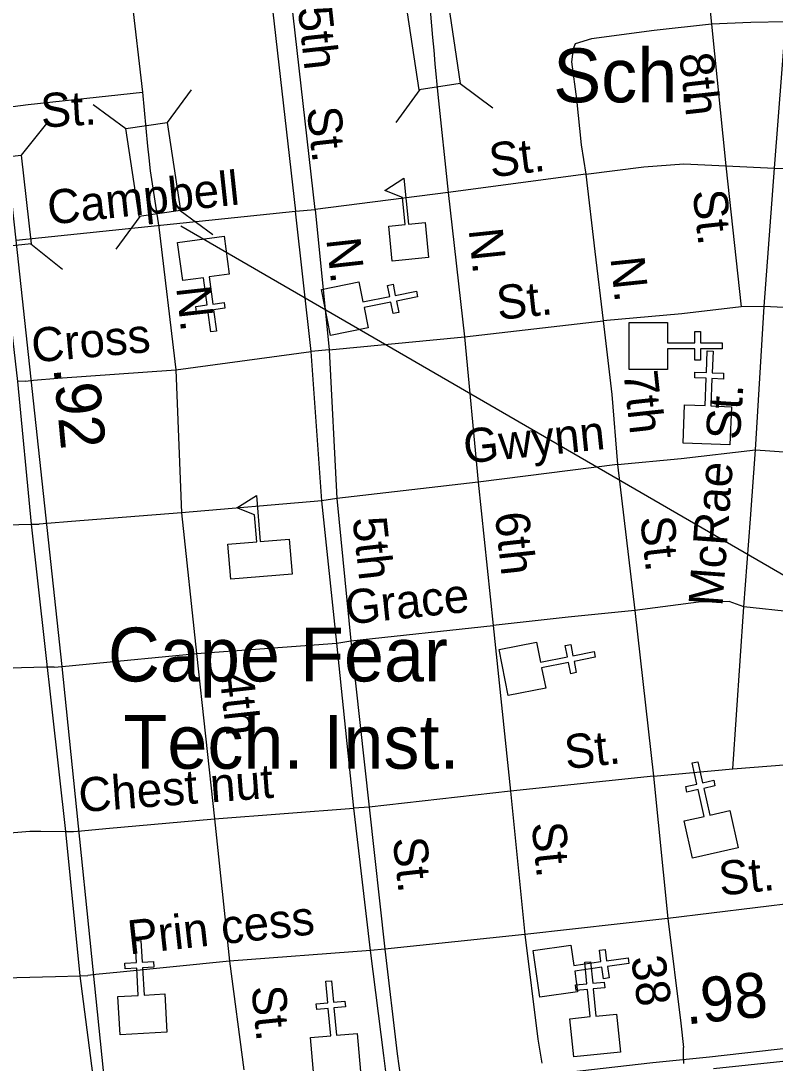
# Model space of a CAD drawing. Extents: x 2290055 to 2389491, y 66597 to 237875.
# Drawn here: x 2318340 to 2320442, y 178595 to 181498 of the extents above; entities that cross this region are included whole.
import ezdxf

# ---------------------------------------------------------------- set-up
doc = ezdxf.new("R2010")
doc.units = 0
for name, color, linetype in [('Exist Cultural Church CELL', 7, 'Continuous'), ('Exist Cultural Educational Facility College or University CELL', 7, 'Continuous'), ('Exist Cultural Educational Facility College or University Label', 7, 'Continuous'), ('Exist Cultural Educational Facility High CELL', 7, 'Continuous'), ('Exist Cultural Educational Facility High Label', 7, 'Continuous'), ('Exist Road Non-System Structure Non-Sys Other CELL', 7, 'Continuous'), ('Exist Road Non-System Structure Non-Sys Other Number Label', 7, 'Continuous'), ('Exist Road Non-System Type 51', 7, 'Continuous'), ('Exist Road Non-System Type 51 Label', 7, 'Continuous'), ('Exist Road Primary US Divided Attributed', 7, 'Continuous'), ('Exist Road Primary US Mileage Hundredths English Label', 7, 'Continuous'), ('Exist Road Secondary Mileage Hundredths English Label', 7, 'Continuous'), ('Exist Road Secondary Structure Standard Bridge CELL', 7, 'Continuous'), ('Exist Road Secondary Type 51 Divided Attributed', 7, 'Continuous')]:
    doc.layers.add(name, color=color, linetype=linetype)

msp = doc.modelspace()

# ---------------------------------------------------------------- linework, layer by layer
at = {"layer": 'Exist Cultural Church CELL'}
for points in [[(2318921, 180792.3), (2318864.6, 180784.4), (2318875, 180709), (2318906.7, 180713.4), (2318908.9, 180697.6), (2318877.2, 180693.2), (2318885.4, 180633.6), (2318869.5, 180631.4), (2318861.3, 180691), (2318829.6, 180686.6), (2318827.4, 180702.5), (2318859.1, 180706.8), (2318848.7, 180782.3), (2318791.6, 180774.5), (2318777.1, 180880), (2318906.5, 180897.8)], [(2319281.9, 180770.4), (2319293.2, 180714.6), (2319367.9, 180729.5), (2319361.6, 180760.9), (2319377.3, 180764), (2319383.5, 180732.6), (2319442.5, 180744.4), (2319445.7, 180728.7), (2319386.7, 180716.9), (2319393, 180685.5), (2319377.3, 180682.4), (2319371, 180713.8), (2319296.4, 180698.9), (2319307.5, 180642.3), (2319203.2, 180621.4), (2319177.6, 180749.5)], [(2320142, 180657.3), (2320142.2, 180600.4), (2320218.3, 180600.4), (2320218.3, 180632.4), (2320234.3, 180632.4), (2320234.3, 180600.4), (2320294.4, 180600.4), (2320294.4, 180584.3), (2320234.3, 180584.3), (2320234.3, 180552.3), (2320218.3, 180552.3), (2320218.3, 180584.3), (2320142.2, 180584.3), (2320142, 180526.7), (2320035.6, 180526.7), (2320035.6, 180657.3)], [(2320189.8, 180428.2), (2320246.7, 180425.9), (2320249.9, 180502), (2320217.9, 180503.4), (2320218.6, 180519.3), (2320250.5, 180518), (2320253, 180578.1), (2320269.1, 180577.4), (2320266.6, 180517.3), (2320298.5, 180516), (2320297.9, 180500), (2320265.9, 180501.4), (2320262.7, 180425.3), (2320320.3, 180422.8), (2320315.9, 180316.4), (2320185.4, 180321.8)], [(2319777, 179767.1), (2319788.3, 179711.3), (2319863, 179726.2), (2319856.7, 179757.6), (2319872.4, 179760.8), (2319878.6, 179729.4), (2319937.6, 179741.2), (2319940.7, 179725.4), (2319881.8, 179713.7), (2319888, 179682.3), (2319872.4, 179679.2), (2319866.1, 179710.5), (2319791.4, 179695.6), (2319802.6, 179639.1), (2319698.2, 179618.2), (2319672.6, 179746.3)], [(2320188.5, 179269.5), (2320244.1, 179281.9), (2320227.6, 179356.3), (2320196.3, 179349.3), (2320192.8, 179364.9), (2320224.1, 179371.8), (2320211, 179430.6), (2320226.7, 179434), (2320239.7, 179375.3), (2320271, 179382.3), (2320274.4, 179366.7), (2320243.2, 179359.7), (2320259.7, 179285.4), (2320316, 179297.8), (2320339.1, 179193.9), (2320211.6, 179165.5)], [(2318610.5, 178779.8), (2318667.4, 178783.2), (2318662.9, 178859.2), (2318630.9, 178857.4), (2318630, 178873.3), (2318662, 178875.2), (2318658.4, 178935.2), (2318674.4, 178936.2), (2318678, 178876.1), (2318709.9, 178878), (2318710.8, 178862.1), (2318678.9, 178860.2), (2318683.4, 178784.2), (2318740.9, 178787.4), (2318747.2, 178681.2), (2318616.8, 178673.5)], [(2319873.1, 178922.9), (2319881.2, 178866.6), (2319956.6, 178877.3), (2319952.1, 178909), (2319967.9, 178911.3), (2319972.4, 178879.6), (2320032, 178888.1), (2320034.2, 178872.2), (2319974.7, 178863.7), (2319979.2, 178832), (2319963.4, 178829.8), (2319958.9, 178861.5), (2319883.5, 178850.7), (2319891.5, 178793.6), (2319786.1, 178778.6), (2319767.7, 178907.9)], [(2319870.2, 178718.3), (2319926.8, 178724.1), (2319919.3, 178799.8), (2319887.4, 178796.6), (2319885.8, 178812.5), (2319917.7, 178815.7), (2319911.7, 178875.6), (2319927.6, 178877.2), (2319933.6, 178817.3), (2319965.4, 178820.5), (2319967, 178804.6), (2319935.2, 178801.4), (2319942.8, 178725.7), (2320000.2, 178731.3), (2320010.8, 178625.4), (2319880.8, 178612.4)], [(2319146.8, 178665.7), (2319203.5, 178670.9), (2319196.6, 178746.8), (2319164.8, 178743.9), (2319163.3, 178759.8), (2319195.2, 178762.7), (2319189.7, 178822.6), (2319205.7, 178824), (2319211.1, 178764.1), (2319243, 178767), (2319244.5, 178751.1), (2319212.6, 178748.2), (2319219.5, 178672.4), (2319276.9, 178677.5), (2319286.6, 178571.5), (2319156.5, 178559.6)]]:
    msp.add_lwpolyline(points, close=True, dxfattribs=at)
at = {"layer": 'Exist Cultural Educational Facility College or University CELL'}
msp.add_lwpolyline([(2318925, 179942.3), (2318916.8, 180039.8), (2318997.6, 180046.6), (2318991.3, 180121.4), (2318942.4, 180141.7), (2318996.5, 180175.4), (2319007.1, 180047.4), (2319087.9, 180054.1), (2319096, 179956.5)], close=True, dxfattribs=at)
at = {"layer": 'Exist Cultural Educational Facility High CELL'}
msp.add_lwpolyline([(2319374.9, 180828.5), (2319365.2, 180925.9), (2319411, 180930.5), (2319403.5, 181005.2), (2319354.3, 181024.7), (2319407.7, 181059.4), (2319420.5, 180931.5), (2319466.4, 180936.1), (2319476.1, 180838.6)], close=True, dxfattribs=at)
at = {"layer": 'Exist Road Non-System Structure Non-Sys Other CELL'}
for p, q in [((2318814.9, 181305.8), (2318747.6, 181214.7)), ((2319452.1, 181306), (2319384.9, 181214.9)), ((2319564.1, 181322.8), (2319655.1, 181255.6)), ((2318542.1, 181264.7), (2318633.1, 181197.5)), ((2318672.1, 180952.7), (2318604.9, 180861.6)), ((2318784, 180969.5), (2318875.1, 180902.3))]:
    msp.add_line(p, q, dxfattribs=at)
for points in [[(2319527.7, 181568), (2319564.6, 181322.9), (2319450.1, 181305.7), (2319413.2, 181550.8)], [(2318747.6, 181214.7), (2318784.6, 180969.6), (2318670.1, 180952.4), (2318633.1, 181197.5)]]:
    msp.add_lwpolyline(points, close=True, dxfattribs=at)
at = {"layer": 'Exist Road Non-System Structure Non-Sys Other Number Label'}
msp.add_line((2318786.3, 180926.4), (2320782.2, 179770.1), dxfattribs=at)
at = {"layer": 'Exist Road Non-System Type 51'}
for p, q in [((2319017.2, 181740.6), (2319105.9, 180967.2)), ((2319160, 180972.3), (2319072.3, 181747.6)), ((2318632.2, 181703.5), (2318678.8, 181299.3)), ((2320264.3, 181488.5), (2320304.2, 181093.9)), ((2320440.3, 181087.5), (2320472.1, 181494.7)), ((2319487.4, 181451.7), (2319490.6, 181416.4)), ((2319490.6, 181416.4), (2319494.1, 181377.9)), ((2318360.5, 181264.9), (2318678.8, 181299.3)), ((2318678.8, 181299.3), (2318692.7, 181148.2)), ((2317861.3, 181201.4), (2318360.5, 181264.9)), ((2318692.7, 181148.2), (2318696.5, 181116.4)), ((2318696.5, 181116.4), (2318700.8, 181080.1)), ((2318700.8, 181080.1), (2318724.3, 180923.4)), ((2319914.9, 181070.6), (2319530.7, 181019.3)), ((2320304.2, 181093.9), (2320440.3, 181087.5)), ((2320304.2, 181093.9), (2320347.7, 180701.5)), ((2320411.6, 180702.1), (2320440.3, 181087.5)), ((2319530.7, 181019.3), (2319160, 180972.3)), ((2319530.7, 181019.3), (2319576.8, 180617.2)), ((2318326.7, 180887.2), (2319105.9, 180967.2)), ((2319105.9, 180967.2), (2319160, 180972.3)), ((2319149.1, 180576.7), (2319105.9, 180967.2)), ((2319160, 180972.3), (2319198.9, 180581)), ((2318724.3, 180923.4), (2318772, 180525.6)), ((2320411.6, 180702.1), (2320347.7, 180701.5)), ((2320387.4, 180303), (2320411.6, 180702.1)), ((2319576.8, 180617.2), (2319962.9, 180662.3)), ((2319198.9, 180581), (2319576.8, 180617.2)), ((2319576.8, 180617.2), (2319614.8, 180212.4)), ((2318772, 180525.6), (2319149.1, 180576.7)), ((2319198.9, 180581), (2319149.1, 180576.7)), ((2319178.7, 180161), (2319149.1, 180576.7)), ((2319198.9, 180581), (2319220.5, 180166.9)), ((2318442.9, 180502.7), (2318772, 180525.6)), ((2318772, 180525.6), (2318787.8, 180127.8)), ((2318353.2, 180494.5), (2318330.6, 180493.6)), ((2318353.2, 180494.5), (2318375.7, 180496.6)), ((2318375.7, 180496.6), (2318375.8, 180496.6)), ((2318375.8, 180496.6), (2318442.9, 180502.7)), ((2320002.7, 180261.8), (2319614.8, 180212.4)), ((2320002.7, 180261.8), (2320051, 179855.5)), ((2319614.8, 180212.4), (2319220.5, 180166.9)), ((2319614.8, 180212.4), (2319656.5, 179813.9)), ((2319178.7, 180161), (2318787.8, 180127.8)), ((2319220.5, 180166.9), (2319178.7, 180161)), ((2319220.3, 179764.5), (2319178.7, 180161)), ((2319220.5, 180166.9), (2319260.1, 179770.4)), ((2318787.8, 180127.8), (2318481.3, 180103.2)), ((2318787.8, 180127.8), (2318829.3, 179735.3)), ((2318300.6, 180094.1), (2318368.5, 180095.5)), ((2318368.5, 180095.5), (2318391, 180096)), ((2318413.8, 180097.8), (2318391, 180096)), ((2318481.3, 180103.2), (2318413.8, 180097.8)), ((2320051, 179855.5), (2320103.4, 179393.5)), ((2320324.5, 179414.1), (2320354.8, 179865.6)), ((2319260.1, 179770.4), (2319656.5, 179813.9)), ((2319656.5, 179813.9), (2319704.7, 179351.8)), ((2318829.3, 179735.3), (2319220.3, 179764.5)), ((2319220.3, 179764.5), (2319260.1, 179770.4)), ((2319268.4, 179304.3), (2319220.3, 179764.5)), ((2319260.1, 179770.4), (2319310.3, 179308)), ((2318522.6, 179706.1), (2318829.3, 179735.3)), ((2318829.3, 179735.3), (2318879.7, 179275.2)), ((2318455, 179699.7), (2318522.6, 179706.1)), ((2318410.3, 179697.1), (2318342.2, 179695.5)), ((2318432.7, 179697.6), (2318410.3, 179697.1)), ((2318432.7, 179697.6), (2318455, 179699.7)), ((2320103.4, 179393.5), (2320324.5, 179414.1)), ((2320324.5, 179414.1), (2320478.2, 179426.4)), ((2320103.4, 179393.5), (2319704.7, 179351.8)), ((2320103.4, 179393.5), (2320143.1, 178997)), ((2319704.7, 179351.8), (2319310.3, 179308)), ((2319704.7, 179351.8), (2319744.8, 178953)), ((2318879.7, 179275.2), (2319268.4, 179304.3)), ((2319310.3, 179308), (2319268.4, 179304.3)), ((2319314.3, 178908.1), (2319268.4, 179304.3)), ((2319310.3, 179308), (2319354.2, 178911.6)), ((2318577, 179247.8), (2318879.7, 179275.2)), ((2318879.7, 179275.2), (2318921.3, 178878.4)), ((2318396, 179240.4), (2318464.6, 179239.8)), ((2318464.6, 179239.8), (2318486.9, 179239.6)), ((2318486.9, 179239.6), (2318509.4, 179241.6)), ((2318509.4, 179241.6), (2318577, 179247.8)), ((2320527.2, 179044), (2320143.1, 178997)), ((2320143.1, 178997), (2319744.8, 178953)), ((2320143.1, 178997), (2320179.6, 178705.8)), ((2319744.8, 178953), (2319354.2, 178911.6)), ((2319744.8, 178953), (2319781.1, 178661.6)), ((2319314.3, 178908.1), (2318921.3, 178878.4)), ((2319354.2, 178911.6), (2319314.3, 178908.1)), ((2319351.7, 178615.7), (2319314.3, 178908.1)), ((2319354.2, 178911.6), (2319389.1, 178620.7)), ((2318921.3, 178878.4), (2318616.6, 178847.8)), ((2318921.3, 178878.4), (2318961.2, 178575.9)), ((2318436.4, 178836.1), (2318504.2, 178838.1)), ((2318504.2, 178838.1), (2318526.8, 178838.8)), ((2318549.2, 178841.1), (2318526.8, 178838.8)), ((2318616.6, 178847.8), (2318549.2, 178841.1)), ((2320179.6, 178705.8), (2320186.8, 178638.5)), ((2319781.1, 178661.6), (2319791.8, 178594.7)), ((2320187, 178615.8), (2320186.8, 178638.5)), ((2319360.3, 178548.7), (2319351.7, 178615.7)), ((2319389.1, 178620.7), (2319398.3, 178553.6)), ((2320187.2, 178593.2), (2320187, 178615.8))]:
    msp.add_line(p, q, dxfattribs=at)
for points in [[(2319452.1, 181794.3), (2319473.8, 181603.2), (2319487.4, 181451.7)], [(2320226.4, 181815.3), (2320241.9, 181705.8), (2320264.3, 181488.5)], [(2320264.3, 181488.5), (2320105.2, 181470.4), (2319929.9, 181447.3), (2319884.5, 181433.4), (2319879.1, 181419.4), (2319874.3, 181383.1), (2319888.6, 181279.6), (2319901.5, 181152.2), (2319914.9, 181070.6)], [(2320472.1, 181494.7), (2320374.4, 181492.8), (2320264.3, 181488.5)], [(2319494.1, 181377.9), (2319501.8, 181292.2), (2319530.7, 181019.3)], [(2319914.9, 181070.6), (2320076.3, 181090.8), (2320187.8, 181099.5), (2320304.2, 181093.9)], [(2319914.9, 181070.6), (2319939.5, 180855.3), (2319962.9, 180662.3)], [(2320440.3, 181087.5), (2320608.5, 181084), (2320836.8, 181078.9)], [(2320347.7, 180701.5), (2320182.4, 180681.2), (2319962.9, 180662.3)], [(2320808.5, 180683.6), (2320609.9, 180691.9), (2320411.6, 180702.1)], [(2319962.9, 180662.3), (2319987.1, 180457.2), (2320002.7, 180261.8)], [(2320002.7, 180261.8), (2320180.3, 180278.7), (2320387.4, 180303)], [(2320354.8, 179865.6), (2320373, 180110.4), (2320387.4, 180303)], [(2320387.4, 180303), (2320586.2, 180288.9), (2320782.5, 180278.6)], [(2320354.8, 179865.6), (2320314.2, 179880), (2320228.3, 179878.6), (2320051, 179855.5)], [(2320051, 179855.5), (2319865.7, 179836.3), (2319656.5, 179813.9)], [(2320745.7, 179841), (2320647.9, 179841.1), (2320493.2, 179851), (2320354.8, 179865.6)], [(2318342.2, 179695.5), (2318318.9, 179695), (2318147.4, 179676.1), (2318008, 179664.7)], [(2318059.8, 179210.5), (2318265, 179232.8), (2318364.8, 179240.7), (2318396, 179240.4)], [(2318101.4, 178814.1), (2318328.8, 178832.9), (2318436.4, 178836.1)]]:
    msp.add_lwpolyline(points, dxfattribs=at)
at = {"layer": 'Exist Road Primary US Divided Attributed'}
for points in [[(2322748.5, 178884.4), (2322612.2, 178870), (2322550.1, 178862), (2322315.1, 178837.6), (2322154.9, 178819.1), (2322092, 178811.9), (2321853.6, 178786.7), (2321765.3, 178775.9), (2321690.5, 178769.4), (2321496.5, 178747.9), (2321330.3, 178727.4), (2321275.7, 178723.4), (2321083.5, 178702.6), (2321034, 178695.4), (2321003.1, 178691.8), (2320969.1, 178689.4), (2320864.3, 178678.2), (2320691.1, 178659.7), (2320576.6, 178646.1), (2320537.7, 178642.9), (2320258.9, 178611.6), (2320101.1, 178595.6), (2319865.6, 178568.4)], [(2320269.9, 178579.3), (2320463.4, 178600.3), (2320550.8, 178609.5), (2320817, 178639.9), (2320978.1, 178657.2), (2321158.7, 178676.8), (2321359.7, 178697.6), (2321463.1, 178709.2), (2321738.2, 178739.7), (2321777.6, 178744.4), (2322092.3, 178778.9), (2322168.2, 178786.9), (2322366.2, 178808.2), (2322442.9, 178816.1), (2322559.5, 178830.6), (2322638.9, 178839), (2322880.4, 178865.8)]]:
    msp.add_lwpolyline(points, dxfattribs=at)
at = {"layer": 'Exist Road Secondary Structure Standard Bridge CELL'}
for p, q in [((2318411.9, 181211.7), (2318341.2, 181123.3)), ((2318368.1, 180876.9), (2318456.4, 180806.2))]:
    msp.add_line(p, q, dxfattribs=at)
msp.add_lwpolyline([(2318341.2, 181123.3), (2318368.6, 180876.9), (2318253.5, 180864.1), (2318226.1, 181110.5)], close=True, dxfattribs=at)
at = {"layer": 'Exist Road Secondary Type 51 Divided Attributed'}
for points in [[(2318027.2, 183059.5), (2318035.9, 182973.4), (2318063.7, 182771.3), (2318099, 182502.1), (2318195.1, 181666.4), (2318330.6, 180493.6), (2318368.5, 180095.5), (2318464.6, 179239.8), (2318504.2, 178838.1), (2318552.9, 178465.3), (2318578.5, 178415.1)], [(2318578.5, 178415.1), (2318578.5, 178492.6), (2318455, 179699.7), (2318326.7, 180887.2), (2318240.3, 181669.1), (2318199.7, 182060.4), (2318135.2, 182503), (2318103.9, 182783.7), (2318082.6, 183062.2)]]:
    msp.add_lwpolyline(points, dxfattribs=at)

# ---------------------------------------------------------------- texts
at = {"layer": 'Exist Cultural Educational Facility College or University Label'}
for s, p in [('Cape Fear', (2318582.7, 179657.7)), ('Tech. Inst.', (2318625.9, 179414.6))]:
    msp.add_text(s, height=150, dxfattribs=at).set_placement(p)
at = {"layer": 'Exist Cultural Educational Facility High Label'}
msp.add_text('Sch.', height=150, dxfattribs=at).set_placement((2319823.5, 181270.7))
at = {"layer": 'Exist Road Non-System Type 51 Label'}
for s, rotation, p in [('5th', 276.2695, (2319112, 181533.5)), ('8th', 276.3795, (2320174.7, 181404.6)), ('St.', 3.401, (2318398, 181200.2)), ('St.', 276.3159, (2319136.7, 181254.5)), ('St.', 7.1267, (2319650.9, 181061.3)), ('Campbell', 6.0878, (2318419, 180929.6)), ('St.', 276.3159, (2320211.9, 181023.3)), ('N.', 275.9865, (2319587.7, 180916.4)), ('N.', 276.3606, (2319191.1, 180889.6)), ('N.', 275.9865, (2319982.9, 180837.3)), ('N.', 276.3606, (2318772.9, 180755.2)), ('St.', 6.0524, (2319670.6, 180664.5)), ('Cross', 5.1747, (2318373.8, 180545.8)), ('7th', 276.2695, (2320019, 180519.1)), ('St.', 86.1936, (2320343.5, 180329.1)), ('Gwynn', 5.9057, (2319578.1, 180264.6)), ('McRae', 85.8115, (2320295.1, 179865)), ('5th', 276.2695, (2319264.2, 180111.9)), ('6th', 276.1497, (2319660.9, 180125.6)), ('St.', 276.3159, (2320065.6, 180114.1)), ('Grace', 5.9915, (2319249.1, 179816.1)), ('4th', 276.3388, (2318893.4, 179679.1)), ('St.', 6.3328, (2319860.1, 179413)), ('Chest nut', 4.2918, (2318504.4, 179293.3)), ('St.', 275.7383, (2319763.1, 179262.6)), ('St.', 276.2695, (2319376.2, 179220.1)), ('St.', 6.1097, (2320289.5, 179060.8)), ('Prin cess', 6.2951, (2318642.9, 178896.9)), ('38', 277.9364, (2320040.2, 178888.2)), ('St.', 275.7383, (2318982.3, 178807))]:
    msp.add_text(s, height=95, rotation=rotation, dxfattribs=at).set_placement(p)
at = {"layer": 'Exist Road Primary US Mileage Hundredths English Label'}
msp.add_text('.98', height=125, rotation=5.8547, dxfattribs=at).set_placement((2320194.5, 178702.1))
at = {"layer": 'Exist Road Secondary Mileage Hundredths English Label'}
msp.add_text('.92', height=125, rotation=275.4307, dxfattribs=at).set_placement((2318430.8, 180531.7))

doc.saveas('drawing.dxf')
